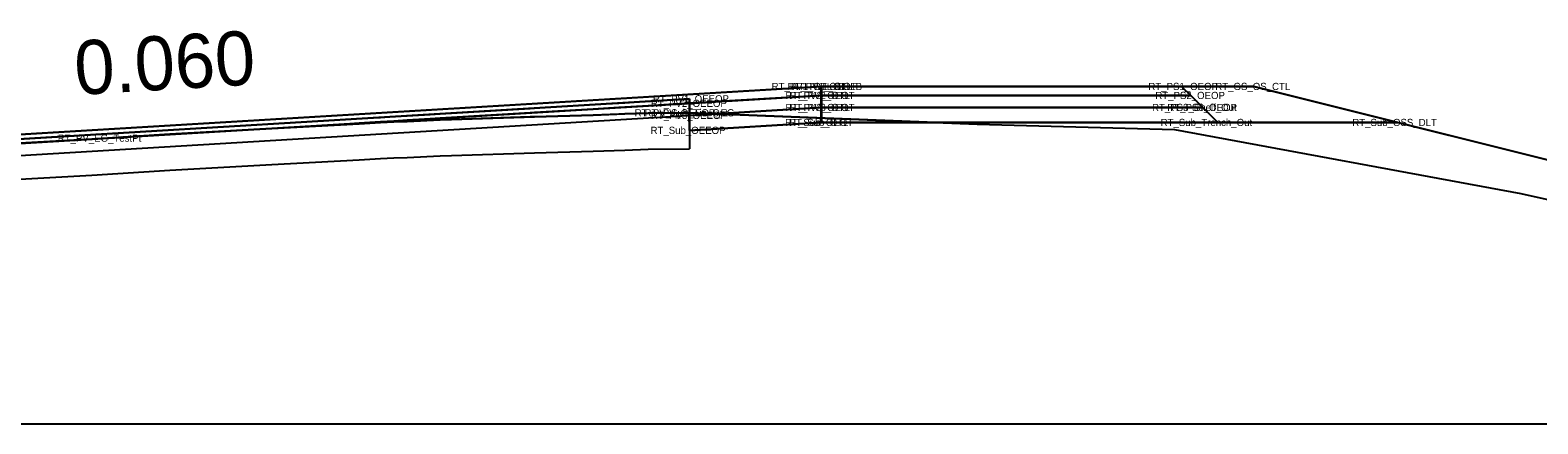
# Model space of a CAD drawing. Extents: x 2177029 to 2201446, y 59897 to 78390.
# Drawn here: x 2199286.78 to 2199328.63, y 67407.31 to 67418.24 of the extents above; entities that cross this region are included whole.
import ezdxf

# ---------------------------------------------------------------- set-up
doc = ezdxf.new("R2010")
doc.units = 0
for name, color, linetype in [('Exist Cross Section Cell', 7, 'Continuous'), ('Exist PHM Roadway Shape', 7, 'Continuous'), ('Exist XS Ground Line', 7, 'Continuous'), ('Old_Level_11', 7, 'Continuous'), ('Prop CMT Conc Surface', 7, 'Continuous'), ('Prop CMT Concrete Structures', 7, 'Continuous'), ('Prop CMT Guardrail Graphics', 7, 'Continuous'), ('Prop CMT Pvmt Course 1', 7, 'Continuous'), ('Prop CMT Pvmt Course 1 CG', 7, 'Continuous'), ('Prop CMT Pvmt Course 2', 7, 'Continuous'), ('Prop CMT Pvmt Course 2 CG', 7, 'Continuous'), ('Prop CMT Pvmt Course 3', 7, 'Continuous'), ('Prop CMT Pvmt Course 4', 7, 'Continuous'), ('Prop CMT Pvmt Surface', 7, 'Continuous'), ('Prop CMT Pvmt Wedge Surface 1', 7, 'Continuous'), ('Prop CMT Slope Grass', 7, 'Continuous'), ('Prop CMT Subgrade Earthwork', 7, 'Continuous'), ('Prop Hatching', 7, 'Continuous'), ('Prop XS Side Slope Text', 7, 'Continuous'), ('Scratch_Level_0', 7, 'Continuous'), ('Scratch_Level_9', 7, 'Continuous')]:
    doc.layers.add(name, color=color, linetype=linetype)

msp = doc.modelspace()

# ---------------------------------------------------------------- linework, layer by layer
at = {"layer": 'Exist Cross Section Cell'}
msp.add_line((2199242.732, 67407.31), (2199442.732, 67407.31), dxfattribs=at)
at = {"layer": 'Exist XS Ground Line'}
msp.add_lwpolyline([(2199285.992, 67415.078), (2199288.156, 67415.199), (2199288.489, 67415.219), (2199290.656, 67415.351), (2199290.987, 67415.37), (2199293.157, 67415.492), (2199293.484, 67415.51), (2199295.915, 67415.639), (2199296.507, 67415.674), (2199296.872, 67415.696), (2199297.244, 67415.71), (2199298.156, 67415.748), (2199298.478, 67415.759), (2199300.781, 67415.836), (2199302.403, 67415.881), (2199303.285, 67415.914), (2199303.935, 67415.933), (2199305.082, 67415.947), (2199313.066, 67415.634), (2199318.547, 67415.487), (2199328.154, 67413.703), (2199333.874, 67412.433)], dxfattribs=at)
at = {"layer": 'Prop CMT Conc Surface'}
for points in [[(2199308.732, 67416.429), (2199308.732, 67416.679)], [(2199272.732, 67414.394), (2199305.082, 67416.335)], [(2199305.082, 67416.21), (2199308.732, 67416.429)], [(2199305.082, 67416.335), (2199305.082, 67416.21)]]:
    msp.add_lwpolyline(points, dxfattribs=at)
at = {"layer": 'Prop CMT Concrete Structures'}
for p, q in [((2199272.732, 67414.519), (2199308.732, 67416.679)), ((2199308.732, 67416.679), (2199308.74, 67416.679)), ((2199308.74, 67416.679), (2199308.742, 67416.679))]:
    msp.add_line(p, q, dxfattribs=at)
at = {"layer": 'Prop CMT Guardrail Graphics'}
for points in [[(2199308.732, 67416.095), (2199308.732, 67416.679)], [(2199272.732, 67413.935), (2199308.732, 67416.095)]]:
    msp.add_lwpolyline(points, dxfattribs=at)
at = {"layer": 'Prop CMT Pvmt Course 1'}
for points in [[(2199293.157, 67415.495), (2199293.484, 67415.515), (2199295.656, 67415.645), (2199295.915, 67415.66), (2199296.507, 67415.696), (2199296.872, 67415.718), (2199297.244, 67415.74), (2199297.883, 67415.778), (2199298.156, 67415.795), (2199298.478, 67415.814), (2199300.656, 67415.945), (2199300.781, 67415.952), (2199302.403, 67416.05), (2199303.119, 67416.093), (2199303.156, 67416.095), (2199303.285, 67416.103), (2199303.935, 67416.142), (2199305.082, 67416.21), (2199305.082, 67416.21)], [(2199305.082, 67416.21), (2199305.082, 67415.947)], [(2199305.082, 67415.947), (2199305.082, 67415.947), (2199303.935, 67415.933), (2199303.285, 67415.914), (2199303.156, 67415.91), (2199303.119, 67415.909), (2199302.403, 67415.881), (2199300.781, 67415.836), (2199300.656, 67415.832), (2199298.478, 67415.759), (2199298.156, 67415.748), (2199297.883, 67415.737), (2199297.244, 67415.71), (2199296.872, 67415.696), (2199296.507, 67415.674), (2199295.915, 67415.639), (2199295.656, 67415.624), (2199293.484, 67415.51), (2199293.157, 67415.492), (2199292.336, 67415.446)], [(2199292.336, 67415.446), (2199293.157, 67415.495)]]:
    msp.add_lwpolyline(points, dxfattribs=at)
at = {"layer": 'Prop CMT Pvmt Course 1 CG'}
for points in [[(2199308.742, 67416.096), (2199319.326, 67416.096)], [(2199308.742, 67415.679), (2199308.742, 67416.096)], [(2199319.326, 67416.096), (2199319.326, 67416.096)], [(2199319.326, 67416.096), (2199319.742, 67415.679)], [(2199319.742, 67415.679), (2199308.742, 67415.679)]]:
    msp.add_lwpolyline(points, dxfattribs=at)
at = {"layer": 'Prop CMT Pvmt Course 2'}
for points in [[(2199305.082, 67415.876), (2199308.732, 67416.095)], [(2199305.082, 67415.46), (2199305.082, 67415.876)], [(2199308.732, 67416.095), (2199308.742, 67416.096)], [(2199308.732, 67415.679), (2199308.732, 67416.095)], [(2199308.732, 67416.095), (2199308.732, 67415.679)], [(2199308.742, 67416.096), (2199308.742, 67415.679)], [(2199308.732, 67415.679), (2199305.082, 67415.46)], [(2199308.742, 67415.679), (2199308.732, 67415.679)]]:
    msp.add_lwpolyline(points, dxfattribs=at)
at = {"layer": 'Prop CMT Pvmt Course 2 CG'}
for points in [[(2199272.732, 67414.519), (2199308.732, 67416.679)], [(2199308.732, 67416.679), (2199308.742, 67416.679)], [(2199308.732, 67416.429), (2199308.732, 67416.679)], [(2199308.732, 67416.679), (2199308.732, 67416.429)], [(2199308.742, 67416.679), (2199308.742, 67416.429)], [(2199305.082, 67416.335), (2199272.732, 67414.394)], [(2199308.732, 67416.429), (2199305.082, 67416.21)], [(2199305.082, 67416.21), (2199305.082, 67416.335)], [(2199308.742, 67416.429), (2199308.732, 67416.429)]]:
    msp.add_lwpolyline(points, dxfattribs=at)
at = {"layer": 'Prop CMT Pvmt Course 3'}
for points in [[(2199305.082, 67415.46), (2199305.067, 67415.947)], [(2199305.082, 67415.46), (2199308.732, 67415.679)], [(2199308.732, 67415.679), (2199308.742, 67415.679)], [(2199308.742, 67415.679), (2199319.742, 67415.679)], [(2199319.742, 67415.679), (2199324.742, 67415.679)]]:
    msp.add_lwpolyline(points, dxfattribs=at)
at = {"layer": 'Prop CMT Pvmt Course 4'}
msp.add_lwpolyline([(2199308.742, 67416.679), (2199318.742, 67416.679)], dxfattribs=at)
at = {"layer": 'Prop CMT Pvmt Surface'}
for points in [[(2199285.992, 67415.19), (2199288.156, 67415.32), (2199288.489, 67415.34), (2199290.656, 67415.47), (2199290.987, 67415.49), (2199293.157, 67415.62), (2199293.484, 67415.64), (2199295.656, 67415.77), (2199295.915, 67415.785), (2199296.507, 67415.821), (2199296.872, 67415.843), (2199297.244, 67415.865), (2199297.883, 67415.903), (2199298.156, 67415.92), (2199298.478, 67415.939), (2199300.656, 67416.07), (2199300.781, 67416.077), (2199302.403, 67416.175), (2199303.119, 67416.218), (2199303.156, 67416.22), (2199303.285, 67416.228), (2199303.935, 67416.267), (2199305.082, 67416.335), (2199305.082, 67416.335)], [(2199305.082, 67416.21), (2199305.082, 67416.21), (2199303.935, 67416.142), (2199303.285, 67416.103), (2199303.156, 67416.095), (2199303.119, 67416.093), (2199302.403, 67416.05), (2199300.781, 67415.952), (2199300.656, 67415.945), (2199298.478, 67415.814), (2199298.156, 67415.795), (2199297.883, 67415.778), (2199297.244, 67415.74), (2199296.872, 67415.718), (2199296.507, 67415.696), (2199295.915, 67415.66), (2199295.656, 67415.645), (2199293.484, 67415.515), (2199293.157, 67415.495), (2199292.336, 67415.446), (2199290.987, 67415.37), (2199290.656, 67415.351), (2199288.489, 67415.219), (2199288.156, 67415.199), (2199285.992, 67415.078)], [(2199305.082, 67416.335), (2199305.082, 67416.21)]]:
    msp.add_lwpolyline(points, dxfattribs=at)
at = {"layer": 'Prop CMT Pvmt Wedge Surface 1'}
for p, q in [((2199305.082, 67415.947), (2199305.082, 67414.947)), ((2199293.484, 67414.51), (2199295.915, 67414.639)), ((2199295.915, 67414.639), (2199296.507, 67414.674)), ((2199296.507, 67414.674), (2199296.872, 67414.696)), ((2199296.872, 67414.696), (2199297.244, 67414.71)), ((2199297.244, 67414.71), (2199298.156, 67414.748)), ((2199298.156, 67414.748), (2199298.478, 67414.759)), ((2199298.478, 67414.759), (2199300.781, 67414.836)), ((2199300.781, 67414.836), (2199302.403, 67414.881)), ((2199302.403, 67414.881), (2199303.285, 67414.914)), ((2199303.285, 67414.914), (2199303.935, 67414.933)), ((2199303.935, 67414.933), (2199305.082, 67414.947)), ((2199305.082, 67414.947), (2199305.082, 67414.947)), ((2199285.992, 67414.078), (2199288.156, 67414.199)), ((2199288.156, 67414.199), (2199288.489, 67414.219)), ((2199288.489, 67414.219), (2199290.656, 67414.351)), ((2199290.656, 67414.351), (2199290.987, 67414.37)), ((2199290.987, 67414.37), (2199293.157, 67414.492)), ((2199293.157, 67414.492), (2199293.484, 67414.51))]:
    msp.add_line(p, q, dxfattribs=at)
at = {"layer": 'Prop CMT Slope Grass'}
for points in [[(2199305.082, 67416.21), (2199308.732, 67416.429)], [(2199305.082, 67415.876), (2199305.082, 67416.21)], [(2199308.732, 67416.095), (2199308.732, 67416.429)], [(2199308.732, 67416.429), (2199308.742, 67416.429)], [(2199308.732, 67416.429), (2199308.732, 67416.095)], [(2199308.742, 67416.429), (2199308.742, 67416.096)], [(2199308.732, 67416.095), (2199305.082, 67415.876)], [(2199308.742, 67416.096), (2199308.732, 67416.095)]]:
    msp.add_lwpolyline(points, dxfattribs=at)
at = {"layer": 'Prop CMT Subgrade Earthwork'}
for points in [[(2199308.732, 67416.429), (2199308.732, 67416.679)], [(2199272.732, 67414.269), (2199308.732, 67416.429)]]:
    msp.add_lwpolyline(points, dxfattribs=at)
at = {"layer": 'Prop Hatching'}
msp.add_lwpolyline([(2199318.742, 67416.679), (2199320.742, 67416.679), (2199353.418, 67408.51)], dxfattribs=at)
at = {"layer": 'Prop XS Side Slope Text'}
msp.add_lwpolyline([(2199285.992, 67415.078), (2199288.156, 67415.199), (2199288.489, 67415.219), (2199290.656, 67415.351), (2199290.987, 67415.37), (2199293.157, 67415.492), (2199293.484, 67415.51), (2199295.915, 67415.639), (2199296.507, 67415.674), (2199296.872, 67415.696), (2199297.244, 67415.71), (2199298.156, 67415.748), (2199298.478, 67415.759), (2199300.781, 67415.836), (2199302.403, 67415.881), (2199303.285, 67415.914), (2199303.935, 67415.933), (2199305.067, 67415.947), (2199311.916, 67415.679), (2199319.742, 67415.679), (2199324.742, 67415.679), (2199320.742, 67416.679), (2199318.742, 67416.679), (2199308.742, 67416.679), (2199272.732, 67414.519)], dxfattribs=at)
for points in [[(2199308.732, 67415.679), (2199311.916, 67415.679), (2199305.067, 67415.947), (2199305.082, 67415.46)], [(2199342.216, 67410.406), (2199344.464, 67410.749), (2199324.742, 67415.679), (2199319.742, 67415.679), (2199311.916, 67415.679), (2199313.066, 67415.634), (2199318.547, 67415.487), (2199328.154, 67413.703), (2199333.874, 67412.433)]]:
    msp.add_lwpolyline(points, close=True, dxfattribs=at)
at = {"layer": 'Scratch_Level_0'}
for points in [[(2199308.742, 67416.429), (2199318.993, 67416.429), (2199319.326, 67416.096)], [(2199308.742, 67416.096), (2199308.742, 67416.429)], [(2199319.326, 67416.096), (2199308.742, 67416.096)]]:
    msp.add_lwpolyline(points, dxfattribs=at)
at = {"layer": 'Scratch_Level_9'}
for points in [[(2199308.742, 67416.679), (2199318.742, 67416.679), (2199318.993, 67416.429)], [(2199308.742, 67416.429), (2199308.742, 67416.679)], [(2199318.993, 67416.429), (2199308.742, 67416.429)]]:
    msp.add_lwpolyline(points, dxfattribs=at)

# ---------------------------------------------------------------- texts
at = {"layer": 'Exist PHM Roadway Shape'}
for s, p in [('RT_PV1_OTL SE LB', (2199307.359, 67416.579)), ('RT_PV1_OEOT', (2199307.801, 67416.579)), ('RT_PV1_OTL', (2199307.909, 67416.579)), ('RT_PS1_OEOP', (2199317.818, 67416.579)), ('RT_GS_OS_CTL', (2199319.675, 67416.579)), ('RT_PV2_OEEOP', (2199304.008, 67416.11)), ('RT_PV1_OEEOP', (2199304.065, 67416.235)), ('RT_PV2_OEOT', (2199307.744, 67416.329)), ('RT_PV2_OTL', (2199307.852, 67416.329)), ('RT_PS2_OEOP', (2199318.011, 67416.329)), ('RT_PV_Sub_Tie_Out', (2199303.557, 67415.847)), ('RT_PV_OEEOP_EG', (2199303.832, 67415.847)), ('RT_PV3_OEEOP', (2199304.008, 67415.776)), ('RT_PV3_OEOT', (2199307.744, 67415.995)), ('RT_PV3_OTL', (2199307.852, 67415.996)), ('RT_PS3_Shelf_Out', (2199317.92, 67415.996)), ('RT_PS3_OEOP', (2199318.345, 67415.996)), ('RT_Sub_OEEOP', (2199303.999, 67415.36)), ('RT_Sub_OEOT', (2199307.735, 67415.579)), ('RT_Sub_OTL', (2199307.843, 67415.579)), ('RT_Sub_Trench_Out', (2199318.158, 67415.579)), ('RT_Sub_OSS_DLT', (2199323.478, 67415.579)), ('RT_PV_EG_TestPt', (2199287.544, 67415.144))]:
    msp.add_text(s, height=0.2, dxfattribs=at).set_placement(p)
at = {"layer": 'Old_Level_11'}
msp.add_text('0.060', height=1.5, rotation=3.4337, dxfattribs=at).set_placement((2199288.052, 67416.44))

doc.saveas('drawing.dxf')
